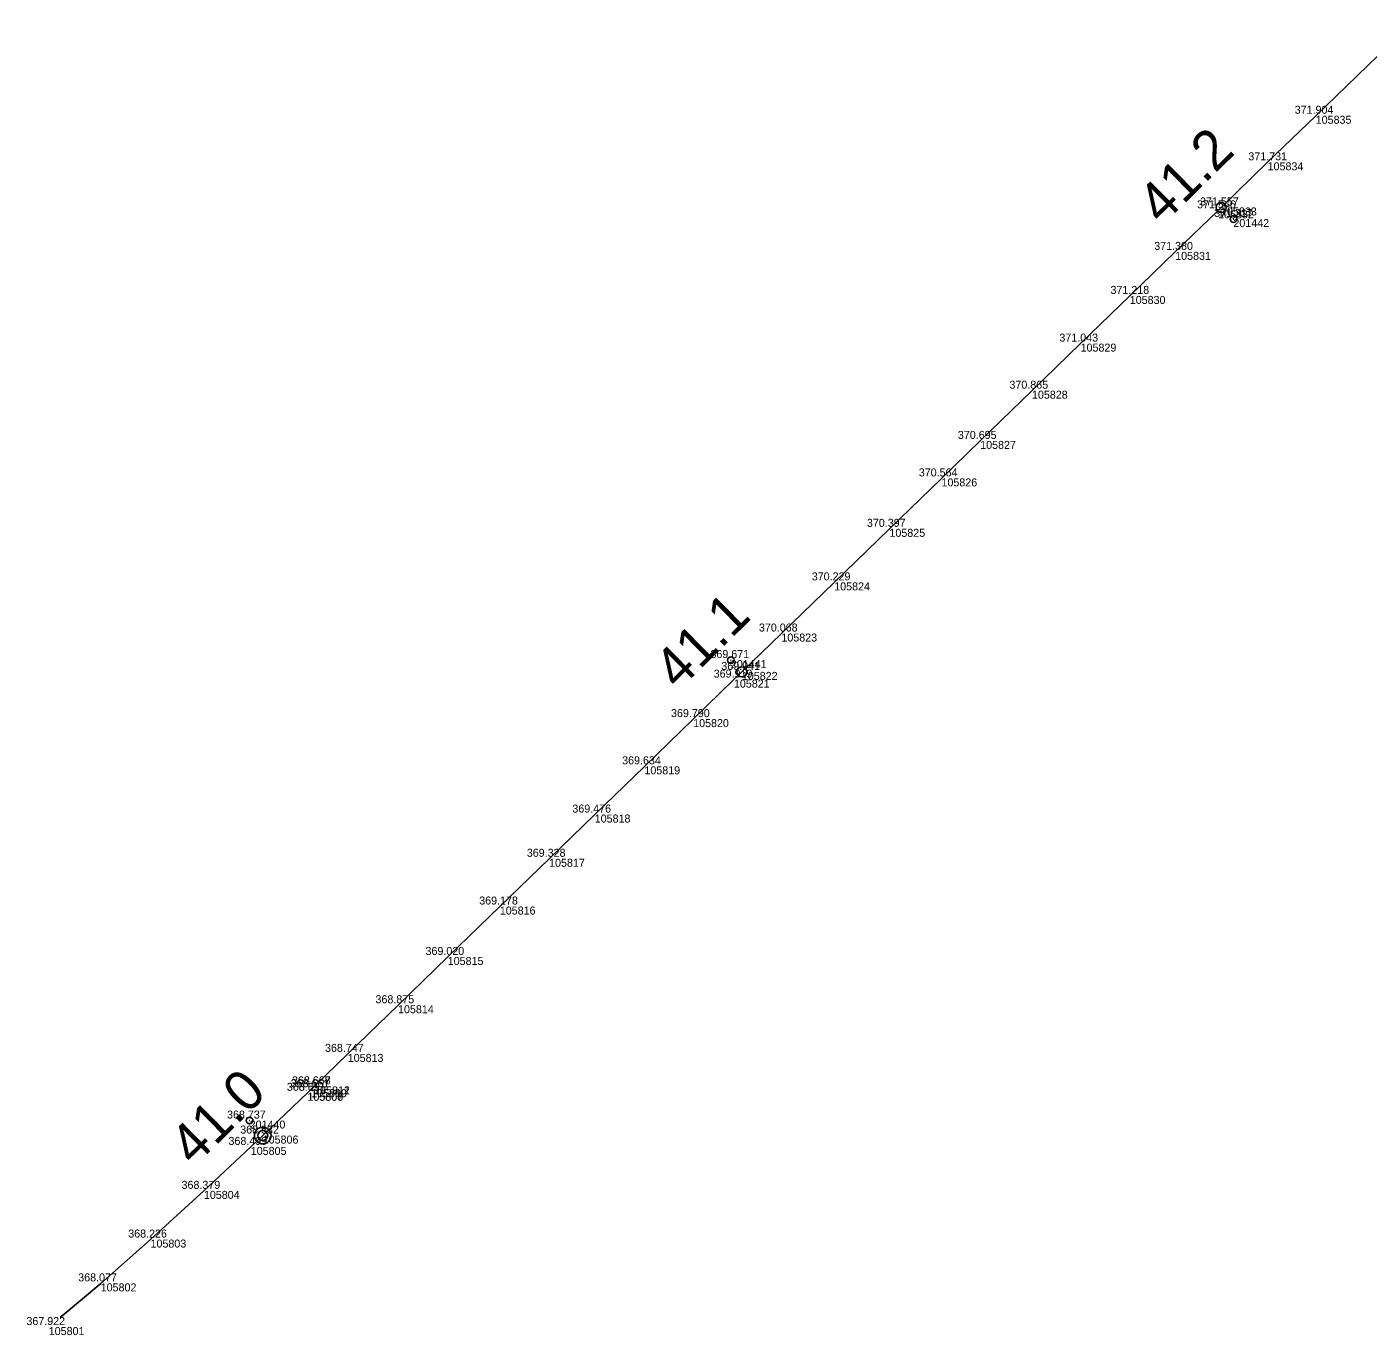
# Model space of a CAD drawing. Extents: x -514522 to -512811, y -1144589 to -1143575.
# Drawn here: x -514522.1 to -514321, y -1144588.8 to -1144392.6 of the extents above; entities that cross this region are included whole.
import ezdxf

# ---------------------------------------------------------------- set-up
doc = ezdxf.new("R2010")
doc.units = 0
for name, color, linetype in [('Vrstva 1', 7, 'Continuous'), ('Vrstva 60', 7, 'Continuous'), ('Vrstva 61', 7, 'Continuous'), ('Vrstva 7', 7, 'Continuous')]:
    doc.layers.add(name, color=color, linetype=linetype)

msp = doc.modelspace()

# ---------------------------------------------------------------- linework, layer by layer
at = {"layer": 'Vrstva 1'}
for p, q in [((-514328.85, -1144405.93), (-514315.09, -1144392.6)), ((-514336.06, -1144412.91), (-514328.85, -1144405.93)), ((-514343.04, -1144419.68), (-514336.06, -1144412.91)), ((-514343.49, -1144420.11), (-514343.04, -1144419.68)), ((-514349.92, -1144426.34), (-514343.49, -1144420.11)), ((-514356.73, -1144432.94), (-514349.92, -1144426.34)), ((-514364.1, -1144440.09), (-514356.73, -1144432.94)), ((-514371.39, -1144447.15), (-514364.1, -1144440.09)), ((-514379.16, -1144454.68), (-514371.39, -1144447.15)), ((-514384.96, -1144460.3), (-514379.16, -1144454.68)), ((-514392.76, -1144467.86), (-514384.96, -1144460.3)), ((-514401.04, -1144475.89), (-514392.76, -1144467.86)), ((-514408.96, -1144483.56), (-514401.04, -1144475.89)), ((-514414.89, -1144489.31), (-514408.96, -1144483.56)), ((-514416.08, -1144490.47), (-514414.89, -1144489.31)), ((-514422.19, -1144496.39), (-514416.08, -1144490.47)), ((-514429.5, -1144503.47), (-514422.19, -1144496.39)), ((-514436.95, -1144510.7), (-514429.5, -1144503.47)), ((-514443.79, -1144517.33), (-514436.95, -1144510.7)), ((-514451.18, -1144524.49), (-514443.79, -1144517.33)), ((-514458.99, -1144532.05), (-514451.18, -1144524.49)), ((-514466.44, -1144539.29), (-514458.99, -1144532.05)), ((-514473.98, -1144546.58), (-514466.44, -1144539.29)), ((-514479.02, -1144551.45), (-514473.98, -1144546.58)), ((-514486.73, -1144558.83), (-514480.03, -1144552.42)), ((-514480.03, -1144552.42), (-514479.46, -1144551.87)), ((-514479.46, -1144551.87), (-514479.02, -1144551.45)), ((-514495.55, -1144567.12), (-514488.52, -1144560.53)), ((-514488.52, -1144560.53), (-514486.73, -1144558.83)), ((-514503.55, -1144574.42), (-514495.55, -1144567.12)), ((-514511.02, -1144580.99), (-514503.55, -1144574.42)), ((-514517.1, -1144586.11), (-514511.02, -1144580.99))]:
    msp.add_line(p, q, dxfattribs=at)
at = {"layer": 'Vrstva 60'}
for p, q in [((-514328.85, -1144405.93), (-514328.85, -1144405.93)), ((-514336.06, -1144412.91), (-514336.06, -1144412.91)), ((-514343.04, -1144419.68), (-514343.04, -1144419.68)), ((-514343.49, -1144420.11), (-514343.49, -1144420.11)), ((-514341.19, -1144421.41), (-514341.19, -1144421.41)), ((-514349.92, -1144426.34), (-514349.92, -1144426.34)), ((-514356.73, -1144432.94), (-514356.73, -1144432.94)), ((-514364.1, -1144440.09), (-514364.1, -1144440.09)), ((-514371.39, -1144447.15), (-514371.39, -1144447.15)), ((-514379.16, -1144454.68), (-514379.16, -1144454.68)), ((-514384.96, -1144460.3), (-514384.96, -1144460.3)), ((-514392.76, -1144467.86), (-514392.76, -1144467.86)), ((-514401.04, -1144475.89), (-514401.04, -1144475.89)), ((-514408.96, -1144483.56), (-514408.96, -1144483.56)), ((-514416.54, -1144487.54), (-514416.54, -1144487.54)), ((-514414.89, -1144489.31), (-514414.89, -1144489.31)), ((-514416.08, -1144490.47), (-514416.08, -1144490.47)), ((-514422.19, -1144496.39), (-514422.19, -1144496.39)), ((-514429.5, -1144503.47), (-514429.5, -1144503.47)), ((-514436.95, -1144510.7), (-514436.95, -1144510.7)), ((-514443.79, -1144517.33), (-514443.79, -1144517.33)), ((-514451.18, -1144524.49), (-514451.18, -1144524.49)), ((-514458.99, -1144532.05), (-514458.99, -1144532.05)), ((-514466.44, -1144539.29), (-514466.44, -1144539.29)), ((-514473.98, -1144546.58), (-514473.98, -1144546.58)), ((-514480.03, -1144552.42), (-514480.03, -1144552.42)), ((-514480.01, -1144552.41), (-514480.01, -1144552.41)), ((-514479.47, -1144551.89), (-514479.47, -1144551.89)), ((-514479.46, -1144551.87), (-514479.46, -1144551.87)), ((-514479.02, -1144551.45), (-514479.02, -1144551.45)), ((-514479.02, -1144551.45), (-514479.02, -1144551.45)), ((-514488.69, -1144556.58), (-514488.69, -1144556.58)), ((-514488.52, -1144560.53), (-514488.52, -1144560.53)), ((-514486.73, -1144558.83), (-514486.73, -1144558.83)), ((-514495.55, -1144567.12), (-514495.55, -1144567.12)), ((-514503.55, -1144574.42), (-514503.55, -1144574.42)), ((-514511.02, -1144580.99), (-514511.02, -1144580.99)), ((-514518.81, -1144587.54), (-514518.81, -1144587.54))]:
    msp.add_line(p, q, dxfattribs=at)
at = {"layer": 'Vrstva 7'}
for p, q in [((-514341.24, -1144421.41), (-514341.14, -1144421.41)), ((-514416.59, -1144487.54), (-514416.49, -1144487.54)), ((-514488.74, -1144556.58), (-514488.64, -1144556.58))]:
    msp.add_line(p, q, dxfattribs=at)
for centre, radius in [((-514343.04, -1144419.68), 0.75), ((-514341.19, -1144421.41), 0.5), ((-514416.54, -1144487.54), 0.5), ((-514414.89, -1144489.31), 0.75), ((-514488.69, -1144556.58), 0.5), ((-514486.73, -1144558.83), 1.25), ((-514486.73, -1144558.83), 0.752)]:
    msp.add_circle(centre, radius, dxfattribs=at)

# ---------------------------------------------------------------- texts
at = {"layer": 'Vrstva 60'}
for s, p in [('105835', (-514328.85, -1144407.13)), ('105834', (-514336.06, -1144414.11)), ('105833', (-514343.04, -1144420.88)), ('105832', (-514343.49, -1144421.31)), ('201442', (-514341.19, -1144422.61)), ('105831', (-514349.92, -1144427.54)), ('105830', (-514356.73, -1144434.14)), ('105829', (-514364.1, -1144441.29)), ('105828', (-514371.39, -1144448.35)), ('105827', (-514379.16, -1144455.88)), ('105826', (-514384.96, -1144461.5)), ('105825', (-514392.76, -1144469.06)), ('105824', (-514401.04, -1144477.09)), ('105823', (-514408.96, -1144484.76)), ('201441', (-514416.54, -1144488.74)), ('105822', (-514414.89, -1144490.51)), ('105821', (-514416.08, -1144491.67)), ('105820', (-514422.19, -1144497.59)), ('105819', (-514429.5, -1144504.67)), ('105818', (-514436.95, -1144511.9)), ('105817', (-514443.79, -1144518.53)), ('105816', (-514451.18, -1144525.69)), ('105815', (-514458.99, -1144533.25)), ('105814', (-514466.44, -1144540.49)), ('105813', (-514473.98, -1144547.78)), ('105807', (-514480.03, -1144553.62)), ('105808', (-514480.01, -1144553.61)), ('105809', (-514479.47, -1144553.09)), ('105810', (-514479.46, -1144553.07)), ('105812', (-514479.02, -1144552.65)), ('105811', (-514479.02, -1144552.65)), ('201440', (-514488.69, -1144557.78)), ('105805', (-514488.52, -1144561.73)), ('105806', (-514486.73, -1144560.03)), ('105804', (-514495.55, -1144568.32)), ('105803', (-514503.55, -1144575.62)), ('105802', (-514511.02, -1144582.19)), ('105801', (-514518.81, -1144588.74))]:
    msp.add_text(s, height=1.2, dxfattribs=at).set_placement(p)
at = {"layer": 'Vrstva 61'}
for s, p in [('371.904', (-514332, -1144405.63)), ('371.731', (-514338.95, -1144412.61)), ('371.546', (-514346.64, -1144419.81)), ('371.557', (-514346.19, -1144419.38)), ('371.317', (-514344.08, -1144421.11)), ('371.380', (-514353.06, -1144426.04)), ('371.218', (-514359.62, -1144432.64)), ('371.043', (-514367.28, -1144439.79)), ('370.865', (-514374.77, -1144446.85)), ('370.695', (-514382.5, -1144454.38)), ('370.564', (-514388.36, -1144460)), ('370.397', (-514396.14, -1144467.56)), ('370.229', (-514404.41, -1144475.59)), ('370.068', (-514412.33, -1144483.26)), ('369.671', (-514419.6, -1144487.24)), ('369.941', (-514417.97, -1144489.01)), ('369.919', (-514419.11, -1144490.17)), ('369.790', (-514425.51, -1144496.09)), ('369.634', (-514432.84, -1144503.17)), ('369.476', (-514440.3, -1144510.4)), ('369.328', (-514447.13, -1144517.03)), ('369.178', (-514454.27, -1144524.19)), ('369.020', (-514462.32, -1144531.75)), ('368.875', (-514469.82, -1144538.99)), ('368.747', (-514477.39, -1144546.28)), ('368.661', (-514482.53, -1144551.59)), ('368.661', (-514482.52, -1144551.57)), ('368.667', (-514482.35, -1144551.15)), ('368.668', (-514482.34, -1144551.15)), ('368.651', (-514483.12, -1144552.12)), ('368.651', (-514483.1, -1144552.11)), ('368.737', (-514492.08, -1144556.28)), ('368.532', (-514490.1, -1144558.53)), ('368.499', (-514491.86, -1144560.23)), ('368.379', (-514498.9, -1144566.82)), ('368.226', (-514506.89, -1144574.12)), ('368.077', (-514514.39, -1144580.69)), ('367.922', (-514522.16, -1144587.24))]:
    msp.add_text(s, height=1.2, dxfattribs=at).set_placement(p)
at = {"layer": 'Vrstva 7'}
for s, p in [('41.2', (-514351.89, -1144422.46)), ('41.1', (-514424.41, -1144492.19)), ('41.0', (-514497.02, -1144563.59))]:
    msp.add_text(s, height=6, rotation=44.5893, dxfattribs=at).set_placement(p)

doc.saveas('drawing.dxf')
